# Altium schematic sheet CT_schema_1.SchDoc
size 718 x 438 mm
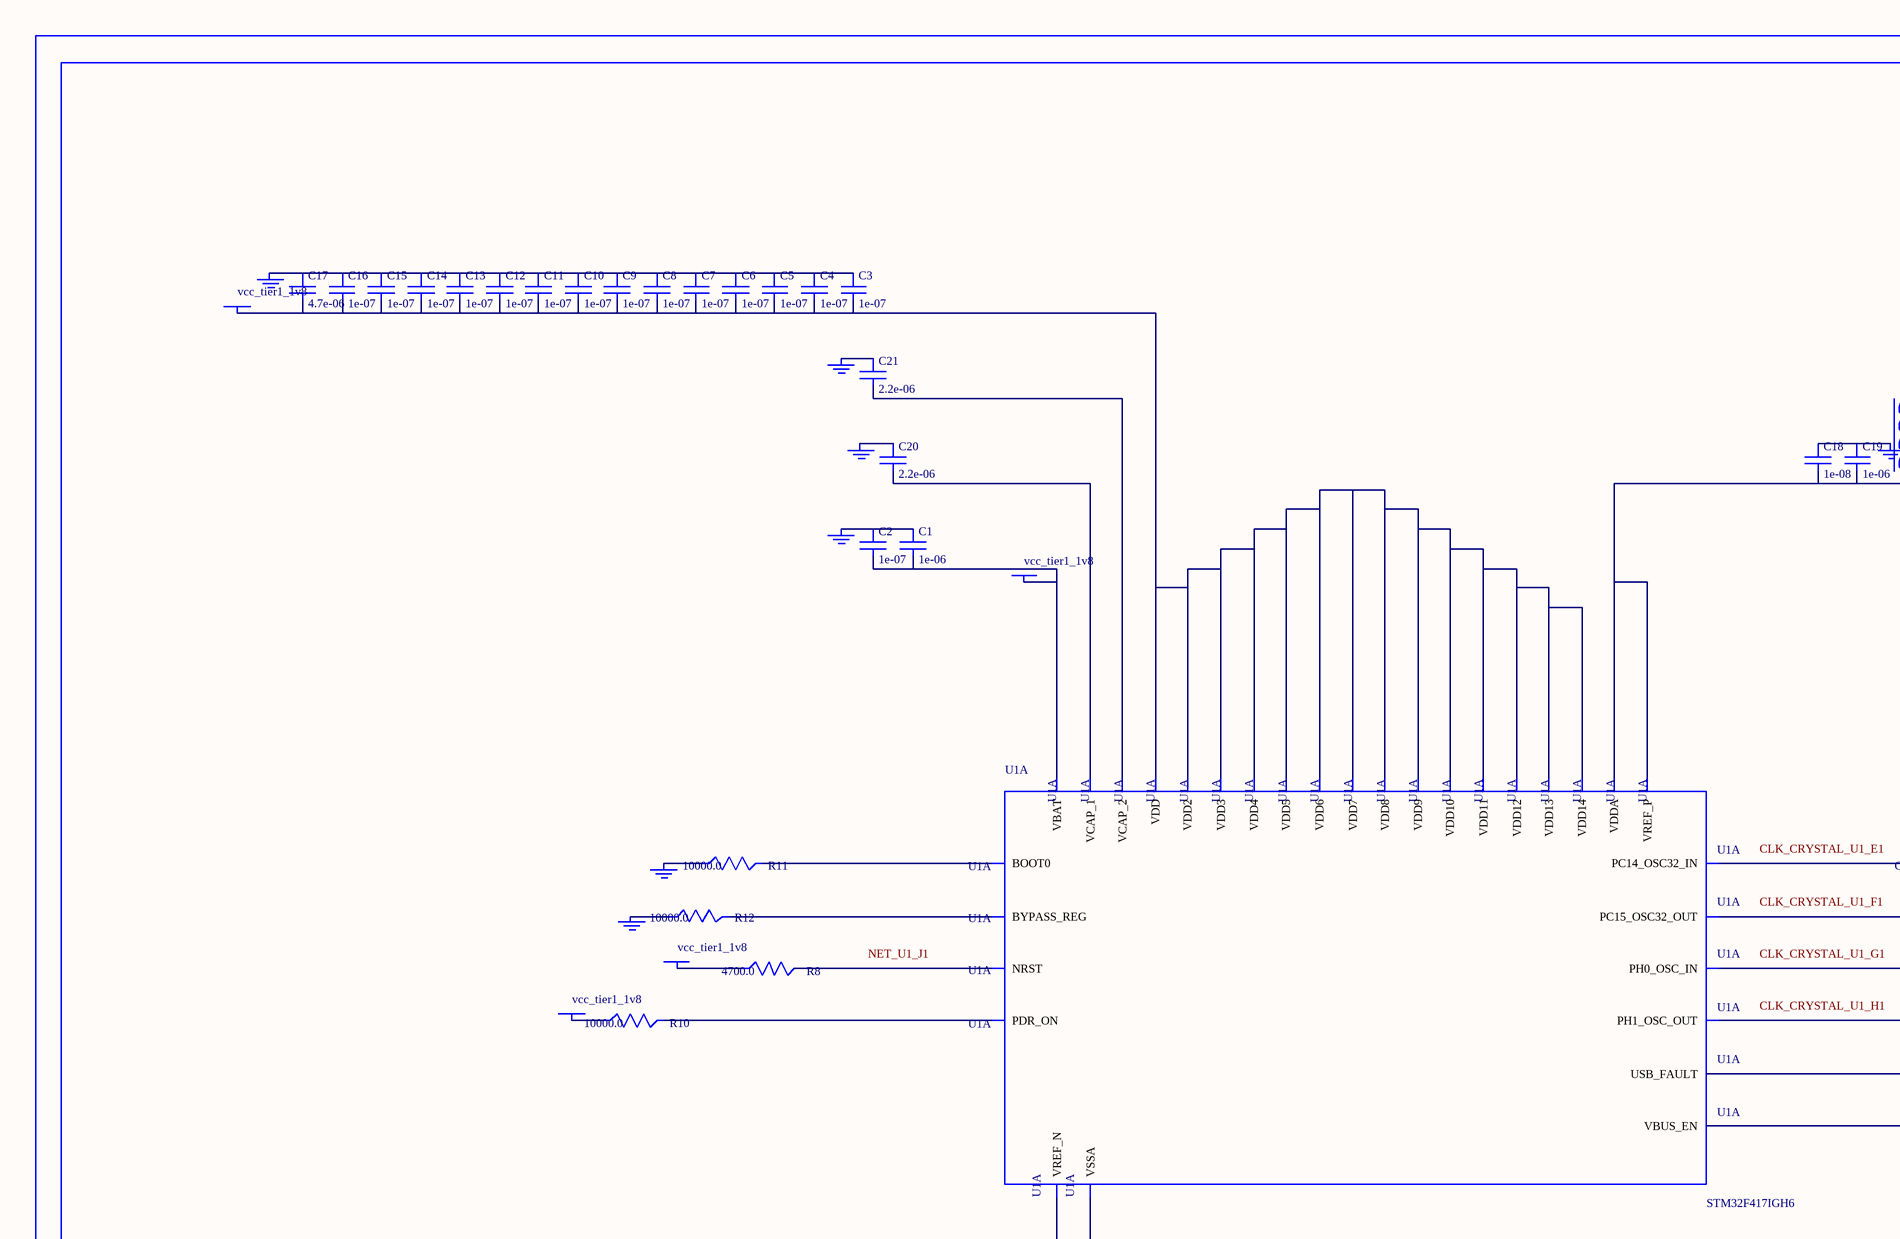
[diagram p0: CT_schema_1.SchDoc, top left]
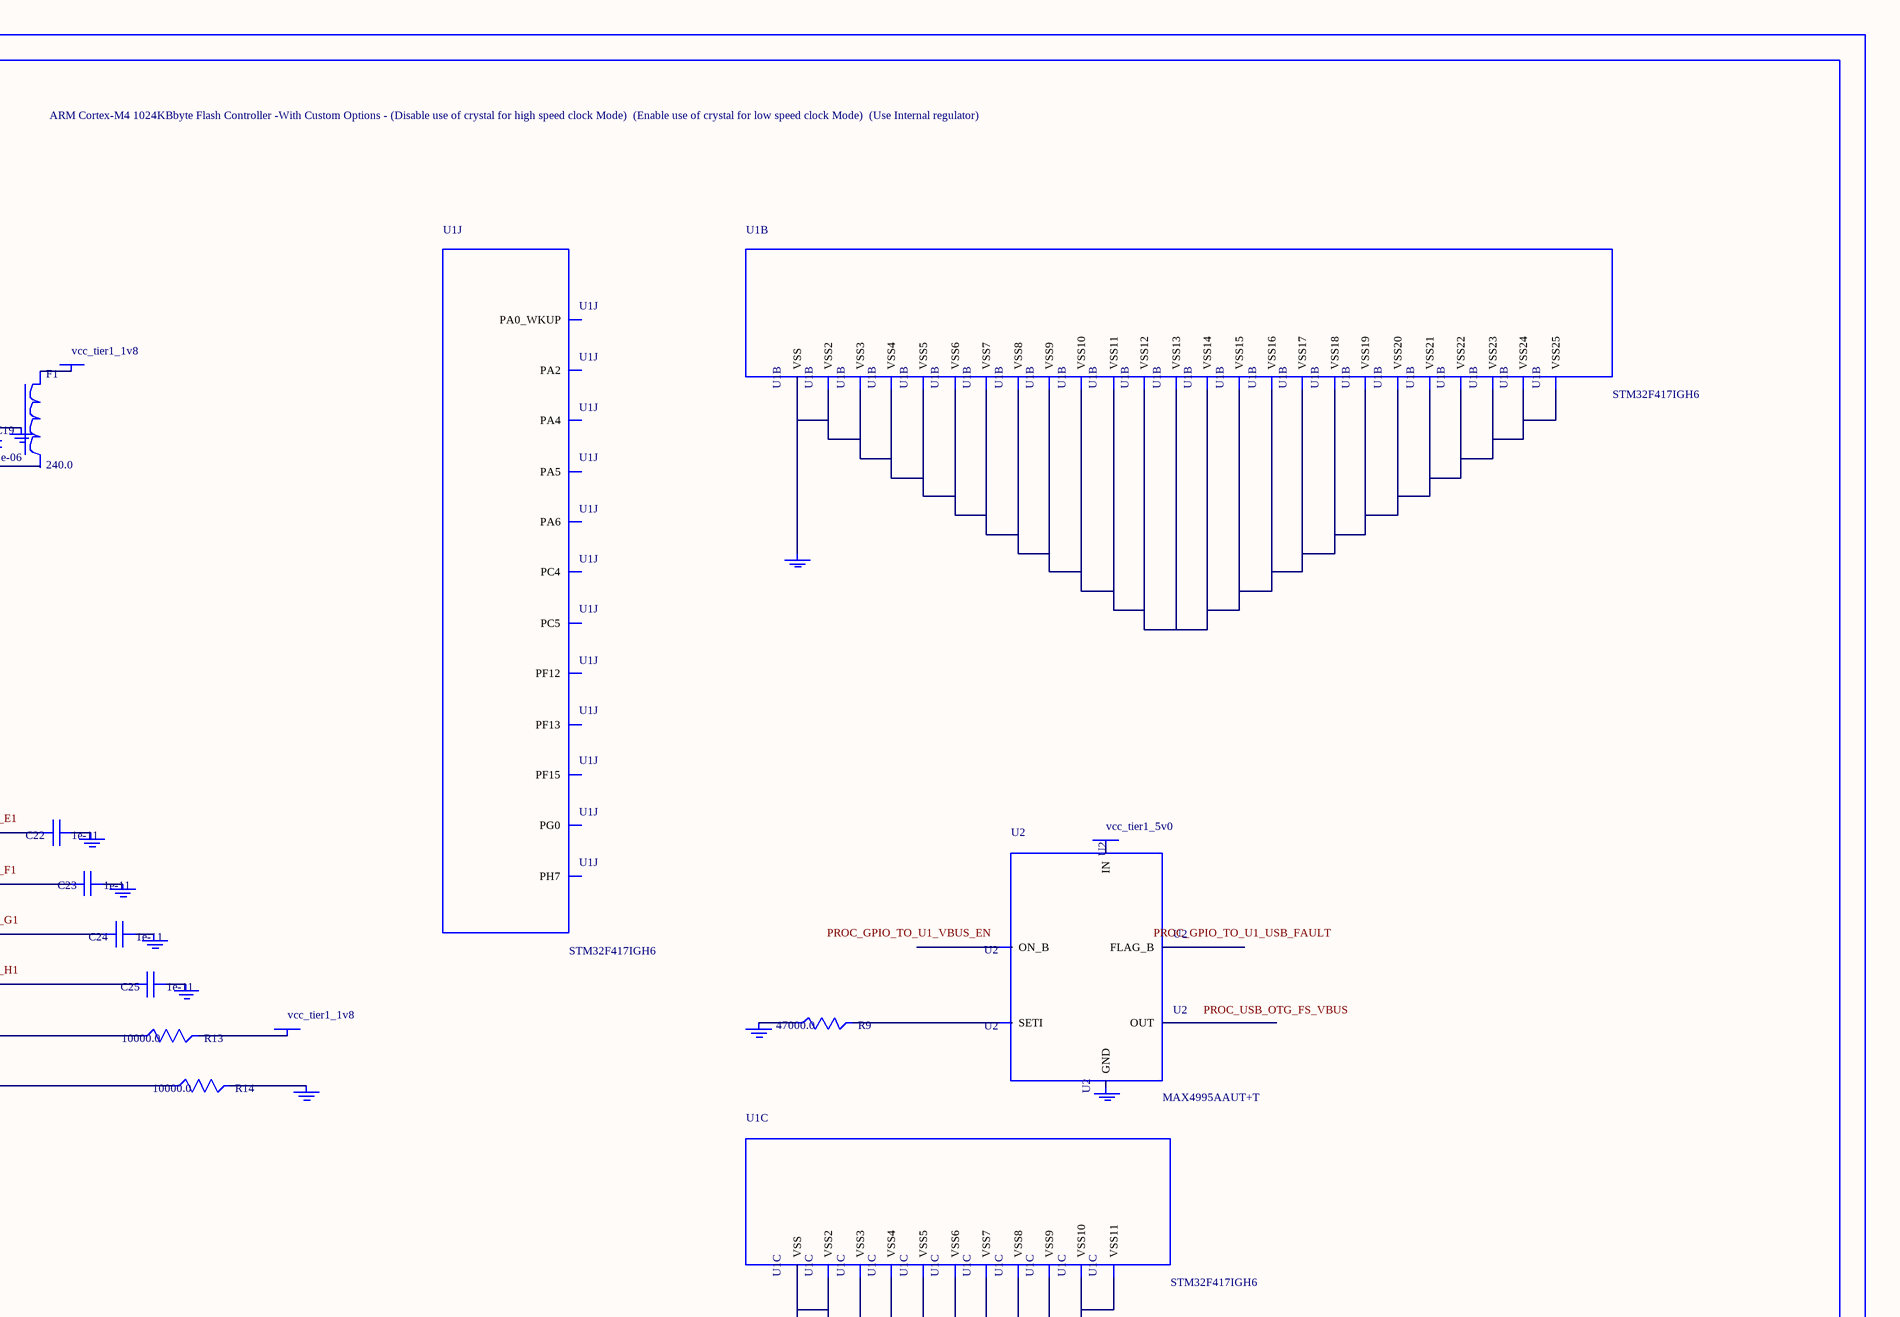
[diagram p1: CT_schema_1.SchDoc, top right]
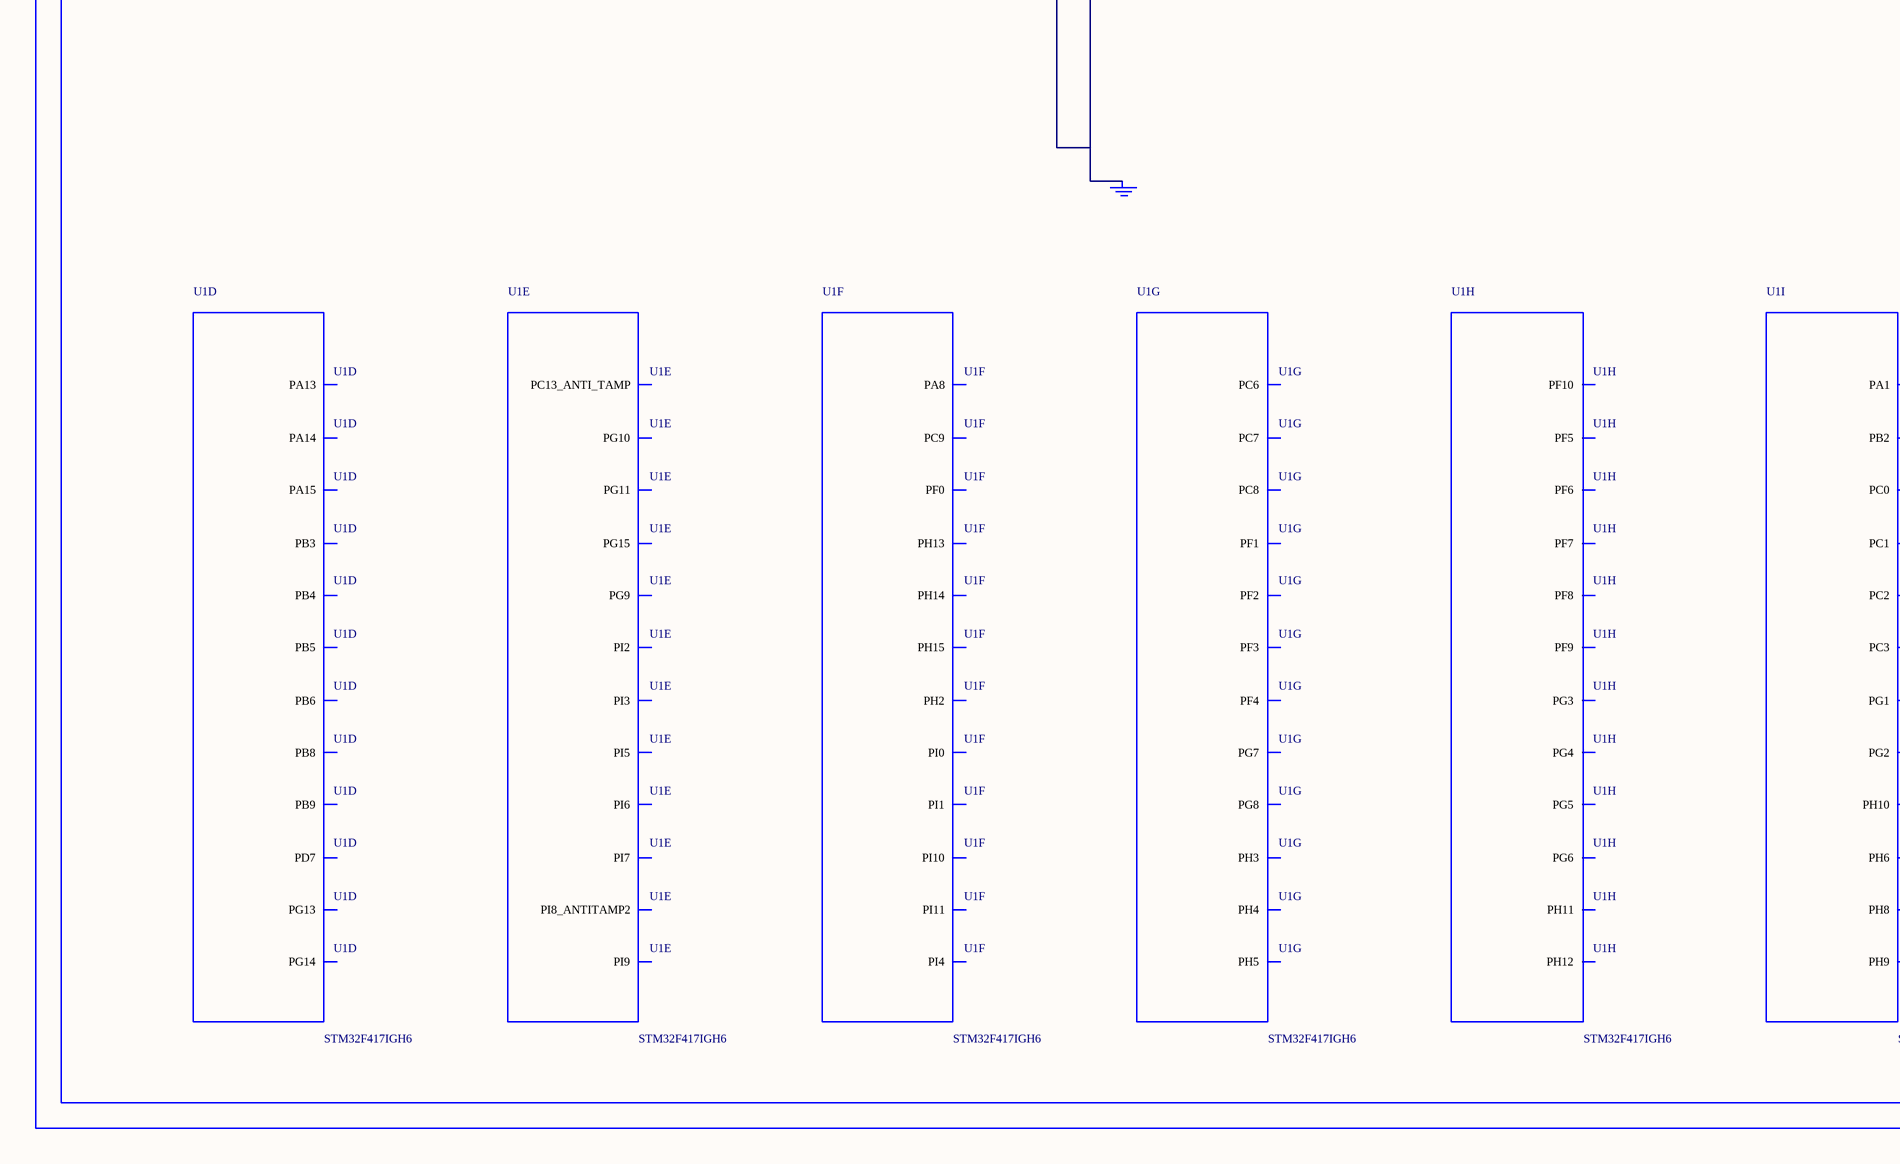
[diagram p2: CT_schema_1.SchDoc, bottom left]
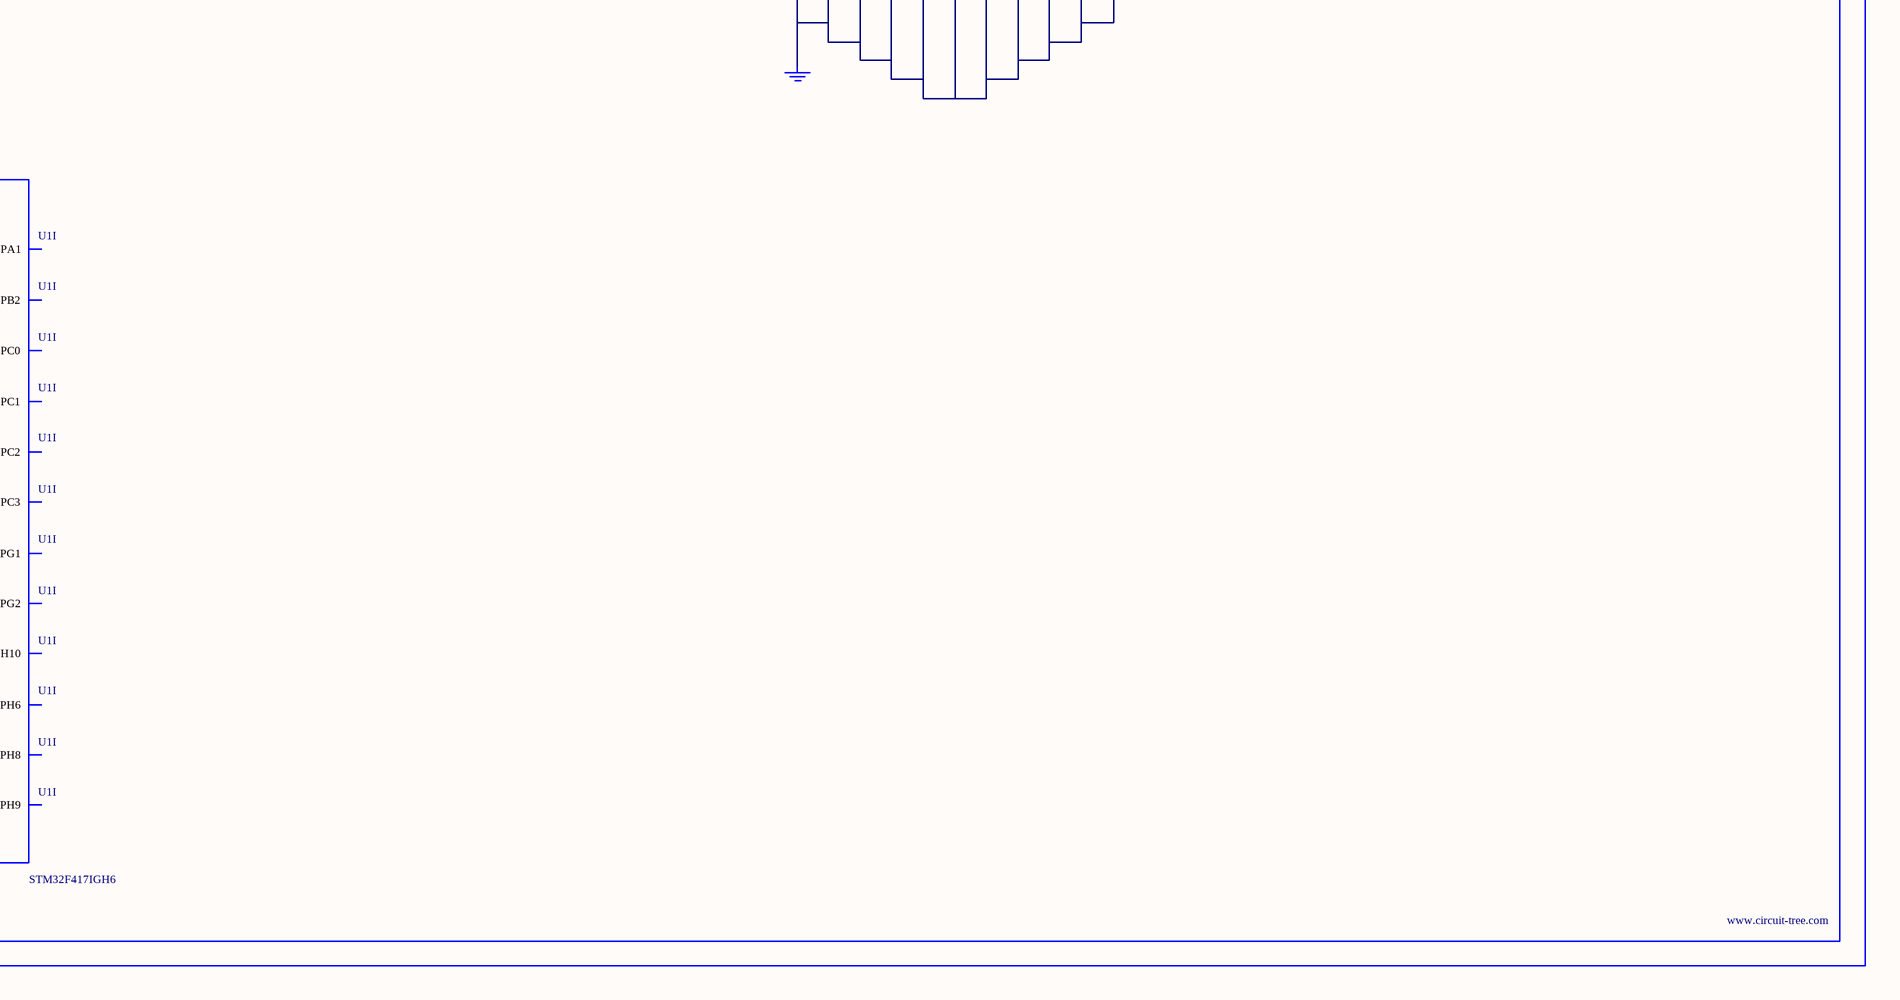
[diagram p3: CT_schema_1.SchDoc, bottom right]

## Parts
BORDER0  (no value)
C1  1e-06  [C0603]
C2  1e-07  [C0603]
C3  1e-07  [C0603]
C4  1e-07  [C0603]
C5  1e-07  [C0603]
C6  1e-07  [C0603]
C7  1e-07  [C0603]
C8  1e-07  [C0603]
C9  1e-07  [C0603]
C10  1e-07  [C0603]
C11  1e-07  [C0603]
C12  1e-07  [C0603]
C13  1e-07  [C0603]
C14  1e-07  [C0603]
C15  1e-07  [C0603]
C16  1e-07  [C0603]
C17  4.7e-06  [C0603]
C18  1e-08  [C0603]
C19  1e-06  [C0603]
C20  2.2e-06  [C0603]
C21  2.2e-06  [C0603]
C22  1e-11  [C0402]
C23  1e-11  [C0402]
C24  1e-11  [C0402]
C25  1e-11  [C0402]
F1  240.0  [L0603]
GND_INSTANCE_0_0  (no value)
GND_INSTANCE_0_1  (no value)
GND_INSTANCE_0_2  (no value)
GND_INSTANCE_0_3  (no value)
GND_INSTANCE_0_4  (no value)
GND_INSTANCE_0_5  (no value)
GND_INSTANCE_0_6  (no value)
GND_INSTANCE_0_7  (no value)
GND_INSTANCE_0_8  (no value)
GND_INSTANCE_0_9  (no value)
GND_INSTANCE_0_10  (no value)
GND_INSTANCE_0_11  (no value)
GND_INSTANCE_0_12  (no value)
GND_INSTANCE_0_13  (no value)
GND_INSTANCE_0_14  (no value)
GND_INSTANCE_0_15  (no value)
GND_INSTANCE_0_16  (no value)
POWER_INSTANCE_0_0  vcc_tier1_1v8
POWER_INSTANCE_0_1  vcc_tier1_1v8
POWER_INSTANCE_0_2  vcc_tier1_1v8
POWER_INSTANCE_0_3  vcc_tier1_1v8
POWER_INSTANCE_0_4  vcc_tier1_1v8
POWER_INSTANCE_0_5  vcc_tier1_1v8
POWER_INSTANCE_0_6  vcc_tier1_5v0
R8  4700.0  [R0603]
R9  47000.0  [R0603]
R10  10000.0  [R0603]
R11  10000.0  [R0603]
R12  10000.0  [R0603]
R13  10000.0  [R0603]
R14  10000.0  [R0603]
U1  STM32F417IGH6  [UFBGA176_25]  (parts A,B,C,D,E,F,G,H,I,J of 15)
U2  MAX4995AAUT+T  [SOT-23-6]

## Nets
NetC1_1: C1.1 C2.1 GND_INSTANCE_0_0.0(GND)
NetC1_2: C1.2 C2.2 POWER_INSTANCE_0_0.0(PWR) U1.C1(VBAT)
NetC3_1: C3.1 C4.1 C5.1 C6.1 C7.1 C8.1 C9.1 C10.1 C11.1 C12.1 C13.1 C14.1 C15.1 C16.1 C17.1 GND_INSTANCE_0_2.0(GND)
NetC3_2: C3.2 C4.2 C5.2 C6.2 C7.2 C8.2 C9.2 C10.2 C11.2 C12.2 C13.2 C14.2 C15.2 C16.2 C17.2 POWER_INSTANCE_0_2.0(PWR) U1.C5(VDD) U1.C7(VDD2) U1.C8(VDD3) U1.C9(VDD4) U1.F3(VDD5) U1.G3(VDD7) U1.G13(VDD6) U1.H13(VDD8) U1.J12(VDD9) U1.J13(VDD10) U1.K4(VDD11) U1.N8(VDD13) U1.N9(VDD14) U1.N10(VDD12)
NetC18_1: C18.1 C19.1 GND_INSTANCE_0_1.0(GND)
NetC18_2: C18.2 C19.2 U1.P1(VREF_P) U1.R1(VDDA)
NetC20_1: C20.1 GND_INSTANCE_0_5.0(GND)
NetC20_2: C20.2 U1.M10(VCAP_1)
NetC21_1: C21.1 GND_INSTANCE_0_6.0(GND)
NetC21_2: C21.2 U1.F13(VCAP_2)
NetC22_1: C22.1 GND_INSTANCE_0_7.0(GND)
NetC22_2: C22.2 U1.E1(PC14_OSC32_IN)
NetC23_1: C23.1 GND_INSTANCE_0_8.0(GND)
NetC23_2: C23.2 U1.F1(PC15_OSC32_OUT)
NetC24_1: C24.1 GND_INSTANCE_0_9.0(GND)
NetC24_2: C24.2 U1.G1(PH0_OSC_IN)
NetC25_1: C25.1 GND_INSTANCE_0_10.0(GND)
NetC25_2: C25.2 U1.H1(PH1_OSC_OUT)
NetF1_1: F1.1 POWER_INSTANCE_0_1.0(PWR)
NetGND_INSTANCE_0_3_0: GND_INSTANCE_0_3.0(GND) R11.1
NetGND_INSTANCE_0_4_0: GND_INSTANCE_0_4.0(GND) R12.1
NetGND_INSTANCE_0_11_0: GND_INSTANCE_0_11.0(GND) R14.2
NetGND_INSTANCE_0_12_0: GND_INSTANCE_0_12.0(GND) U1.M1(VSSA) U1.N1(VREF_N)
NetGND_INSTANCE_0_13_0: GND_INSTANCE_0_13.0(GND) U1.D5(VSS) U1.D7(VSS2) U1.D8(VSS3) U1.D9(VSS4) U1.F2(VSS7) U1.F6(VSS8) U1.F7(VSS9) U1.F8(VSS10) U1.F9(VSS11) U1.F10(VSS5) U1.F12(VSS6) U1.G2(VSS14) U1.G6(VSS15) U1.G7(VSS16) U1.G8(VSS17) U1.G9(VSS18) U1.G10(VSS12) U1.G12(VSS13) U1.H6(VSS21) U1.H7(VSS22) U1.H8(VSS23) U1.H9(VSS24) U1.H10(VSS19) U1.H12(VSS20) U1.J10(VSS25)
NetGND_INSTANCE_0_14_0: GND_INSTANCE_0_14.0(GND) U1.J6(VSS) U1.J7(VSS2) U1.J8(VSS3) U1.J9(VSS4) U1.K6(VSS6) U1.K7(VSS7) U1.K8(VSS8) U1.K9(VSS9) U1.K10(VSS5) U1.M8(VSS10) U1.M9(VSS11)
NetGND_INSTANCE_0_15_0: GND_INSTANCE_0_15.0(GND) R9.1
NetPOWER_INSTANCE_0_3_0: POWER_INSTANCE_0_3.0(PWR) R10.1
NetPOWER_INSTANCE_0_4_0: POWER_INSTANCE_0_4.0(PWR) R13.2
NetPOWER_INSTANCE_0_5_0: POWER_INSTANCE_0_5.0(PWR) R8.1
NetR8_2: R8.2 U1.J1(NRST)
NetR9_2: R9.2 U2.3(SETI)
NetR10_2: R10.2 U1.C6(PDR_ON)
NetR11_2: R11.2 U1.D6(BOOT0)
NetR12_2: R12.2 U1.L4(BYPASS_REG)
NetR13_1: R13.1 U1.A4(USB_FAULT)
NetR14_1: R14.1 U1.A3(VBUS_EN)

Not connected (* = marked no-connect by the designer): F1 2; GND_INSTANCE_0_16 0(GND); POWER_INSTANCE_0_6 0(PWR); U1 A5(PB8) A6(PB5) A7(PG14) A8(PG13) A9(PB4) A10(PB3) A11(PD7) A13(PA15) A14(PA14) A15(PA13) B4(PB9) B6(PB6) B7(PG15) B9(PG11) B10(PG10) C2(PI7) C3(PI6) C4(PI5) C10(PG9) C13(PI3) C14(PI2) D1(PC13_ANTI_TAMP) D2(PI8_ANTITAMP2) D3(PI9) D4(PI4) D13(PH15) D14(PI1) E2(PF0) E3(PI10) E4(PI11) E12(PH13) E13(PH14) E14(PI0) F4(PH2) F14(PC9) F15(PA8) G4(PH3) G14(PC8) G15(PC7) H2(PF2) H3(PF1) H4(PH4) H14(PG8) H15(PC6) J2(PF3) J3(PF4) J4(PH5) J14(PG7) J15(PG6) K1(PF7) K2(PF6) K3(PF5) K12(PH12) K13(PG5) K14(PG4) K15(PG3) L1(PF10) L2(PF9) L3(PF8) L12(PH11) L13(PH10) L15(PG2) M2(PC0) M3(PC1) M4(PC2) M5(PC3) M6(PB2) M7(PG1) M11(PH6) M12(PH8) M13(PH9) N2(PA1) N3(PA0_WKUP) N4(PA4) N5(PC4) N6(PF13) N7(PG0) N12(PH7) P2(PA2) P3(PA6) P4(PA5) P5(PC5) P6(PF12) P7(PF15); U2 1(OUT) 2(GND) 4(ON_B) 5(IN) 6(FLAG_B)

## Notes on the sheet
- Labels drawn without touching a wire or pin: CLK_CRYSTAL_U1_E1, CLK_CRYSTAL_U1_F1, CLK_CRYSTAL_U1_G1, CLK_CRYSTAL_U1_H1, NET_U1_J1, PROC_GPIO_TO_U1_USB_FAULT, PROC_GPIO_TO_U1_VBUS_EN, PROC_USB_OTG_FS_VBUS

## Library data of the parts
BORDER0 = BORDER_PAGE0
C1 C19 = C0603C105K3RACTU
C2-C16 = 06035C104K4Z2A
C17 = GRM188R6YA475KE15D
C18 = 06035C103K4Z2A
C20 C21 = C0603C225K8RACTU
C22-C25 = C0402C100K3GACTU
F1 = Z0603C241ASMST
GND_INSTANCE_0_0-GND_INSTANCE_0_16 = GND
POWER_INSTANCE_0_0-POWER_INSTANCE_0_6 = PWR
R8 = RC0603JR-074K7L
R9 = RC0603JR-0747KL
R10-R14 = RC0603JR-0710KL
